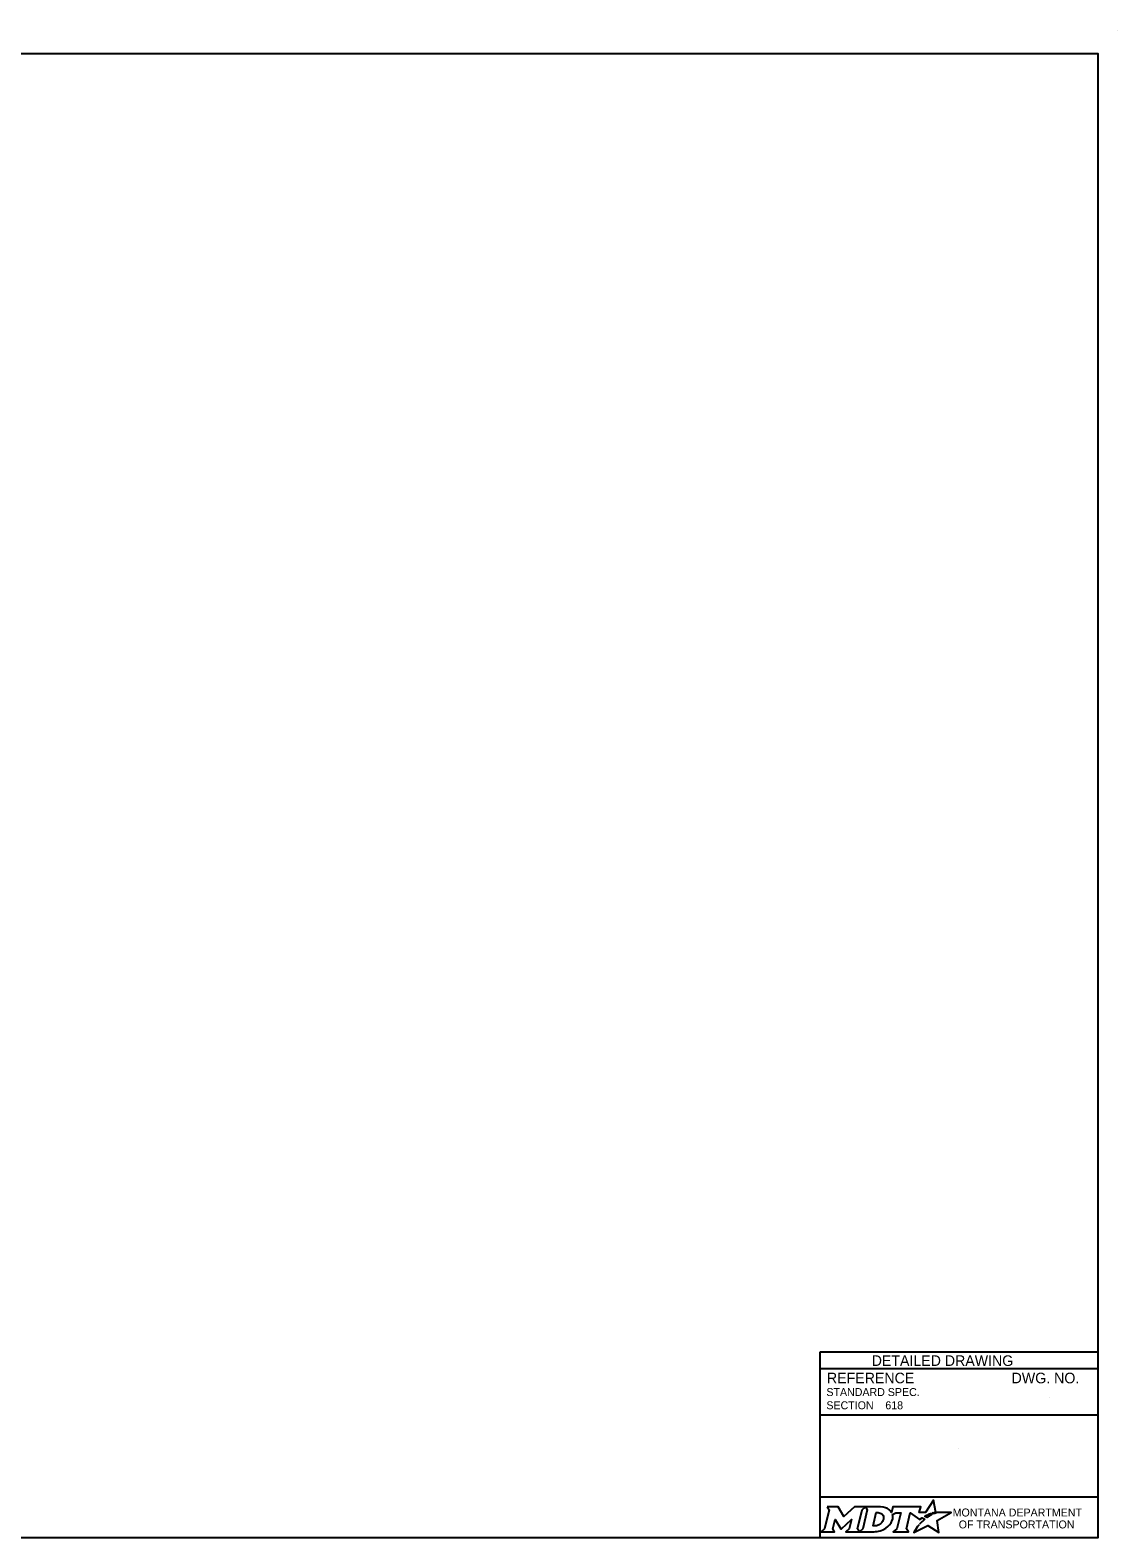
# Model space of a CAD drawing. Extents: x 49991.4 to 50021, y 49987.6 to 50011.4.
# Drawn here: x 50008.69 to 50016.9, y 49987.8 to 49999.18 of the extents above; entities that cross this region are included whole.
import ezdxf

# ---------------------------------------------------------------- set-up
doc = ezdxf.new("R2010")
doc.units = 0
for name, color, linetype in [('Default', 7, 'Continuous'), ('Level 1', 7, 'Continuous'), ('Level 2', 7, 'Continuous'), ('Level 5', 7, 'Continuous')]:
    doc.layers.add(name, color=color, linetype=linetype)

msp = doc.modelspace()

# ---------------------------------------------------------------- linework, layer by layer
at = {"layer": 'Default'}
for points in [[(50015.513, 49987.981), (50015.502, 49987.987), (50015.514, 49987.99), (50015.526, 49987.991), (50015.508, 49988.082), (50015.449, 49987.99), (50015.401, 49987.99), (50015.412, 49988.034), (50015.202, 49988.034), (50015.192, 49987.991), (50015.186, 49988)], [(50014.706, 49988.034), (50014.72, 49988.01), (50014.686, 49987.867), (50014.66, 49987.845), (50014.762, 49987.845), (50014.749, 49987.867), (50014.765, 49987.937), (50014.809, 49987.868), (50014.814, 49987.868), (50014.889, 49987.938), (50014.872, 49987.867), (50014.848, 49987.845), (50014.949, 49987.845), (50014.936, 49987.868), (50014.969, 49988.011)], [(50014.969, 49988.011), (50014.994, 49988.034), (50014.912, 49988.034), (50014.832, 49987.961), (50014.788, 49988.034), (50014.706, 49988.034)], [(50015.108, 49988.034), (50014.994, 49988.034), (50015.009, 49988.011), (50014.975, 49987.867), (50014.949, 49987.845), (50015.06, 49987.845)], [(50015.132, 49987.947), (50015.13, 49987.939), (50015.127, 49987.93), (50015.123, 49987.922), (50015.118, 49987.914), (50015.111, 49987.907), (50015.103, 49987.901), (50015.095, 49987.896), (50015.086, 49987.892), (50015.077, 49987.89), (50015.067, 49987.889), (50015.052, 49987.889), (50015.075, 49987.989), (50015.091, 49987.989), (50015.099, 49987.988), (50015.106, 49987.986), (50015.113, 49987.983), (50015.119, 49987.979), (50015.124, 49987.974), (50015.128, 49987.968), (50015.13, 49987.962), (50015.132, 49987.955), (50015.132, 49987.952), (50015.132, 49987.947)], [(50015.199, 49987.975), (50015.224, 49987.988), (50015.261, 49987.988), (50015.232, 49987.867), (50015.205, 49987.845), (50015.321, 49987.845), (50015.304, 49987.867), (50015.332, 49987.988), (50015.403, 49987.936), (50015.424, 49987.951), (50015.444, 49987.94)], [(50015.388, 49987.884), (50015.373, 49987.86), (50015.368, 49987.852), (50015.362, 49987.844), (50015.36, 49987.839), (50015.465, 49987.893), (50015.549, 49987.838), (50015.536, 49987.93), (50015.643, 49987.989), (50015.594, 49987.989), (50015.564, 49987.99), (50015.543, 49987.99), (50015.536, 49987.989), (50015.531, 49987.987), (50015.523, 49987.985), (50015.513, 49987.981)], [(50015.462, 49987.954), (50015.46, 49987.952), (50015.442, 49987.961), (50015.452, 49987.967), (50015.456, 49987.969), (50015.465, 49987.973), (50015.47, 49987.976), (50015.478, 49987.979), (50015.485, 49987.982), (50015.497, 49987.974), (50015.493, 49987.972), (50015.489, 49987.97), (50015.484, 49987.967), (50015.479, 49987.965), (50015.478, 49987.963), (50015.475, 49987.962), (50015.472, 49987.96), (50015.47, 49987.959), (50015.467, 49987.957), (50015.465, 49987.955), (50015.462, 49987.954)], [(50015.106, 49987.852), (50015.114, 49987.855), (50015.127, 49987.86), (50015.148, 49987.871)], [(50015.402, 49987.9), (50015.402, 49987.9)]]:
    msp.add_lwpolyline(points, dxfattribs=at)
for centre, radius, start, end in [((50015.087, 49987.973), 0.118, 300.9103, 339.1383), ((50015.131, 49987.955), 0.0709, 339.5329, 15.8582)]:
    msp.add_arc(centre, radius, start, end, dxfattribs=at)
for centre, major_axis, ratio, start_param, end_param in [((50015.106, 49987.986), (0.0834, -0.0037), 0.568097, 0.61298, 1.570796), ((50015.161, 49987.994), (0.0361, -0.0295), 0.469099, 1.225588, 1.570796), ((50015.433, 49987.93), (-0.0112, -0.0097), 0.021651, 3.157348, 6.283185), ((50015.06, 49987.993), (0, 0.148), 0.987302, 3.139398, 3.456847), ((50015.395, 49987.892), (-0.00694, -0.00806), 0.008222, 0, 3.137361), ((50015.412, 49987.911), (-0.0098, -0.0102), 0.016458, 3.141593, 6.279097)]:
    msp.add_ellipse(centre, major_axis=major_axis, ratio=ratio, start_param=start_param, end_param=end_param, dxfattribs=at)
at = {"layer": 'Level 1'}
for p, q in [((50016.9, 49999.176), (50016.9, 49999.176)), ((50016.386, 49988.859), (50016.386, 49988.859)), ((50015.144, 49988.799), (50015.144, 49988.799)), ((50015.7, 49988.475), (50015.7, 49988.475))]:
    msp.add_line(p, q, dxfattribs=at)
msp.add_lwpolyline([(49999.384, 49998.999), (50016.75, 49998.999), (50016.75, 49987.799), (49999.384, 49987.799)], close=True, dxfattribs=at)
at = {"layer": 'Level 5'}
for p, q in [((50016.75, 49989.199), (50014.65, 49989.199)), ((50014.65, 49989.199), (50014.65, 49987.799)), ((50016.75, 49989.074), (50014.65, 49989.074)), ((50016.386, 49988.859), (50016.386, 49988.859)), ((50016.75, 49988.724), (50014.65, 49988.724)), ((50015.144, 49988.799), (50015.144, 49988.799)), ((50015.7, 49988.475), (50015.7, 49988.475)), ((50016.75, 49988.106), (50014.65, 49988.106))]:
    msp.add_line(p, q, dxfattribs=at)

# ---------------------------------------------------------------- texts
at = {"layer": 'Default'}
for s, p in [('MONTANA DEPARTMENT', (50015.653, 49987.96)), ('OF TRANSPORTATION', (50015.699, 49987.87))]:
    msp.add_text(s, height=0.06, rotation=360, dxfattribs=at).set_placement(p)
at = {"layer": 'Level 2'}
msp.add_text('618', height=0.06, dxfattribs=at).set_placement((50015.145, 49988.769))
at = {"layer": 'Level 5'}
for s, height, p in [('DETAILED DRAWING', 0.0799, (50015.042, 49989.096)), ('REFERENCE', 0.08, (50014.704, 49988.965)), ('DWG. NO.', 0.08, (50016.098, 49988.965)), ('STANDARD SPEC.', 0.06, (50014.7, 49988.869)), ('SECTION', 0.06, (50014.7, 49988.769))]:
    msp.add_text(s, height=height, dxfattribs=at).set_placement(p)

doc.saveas('drawing.dxf')
